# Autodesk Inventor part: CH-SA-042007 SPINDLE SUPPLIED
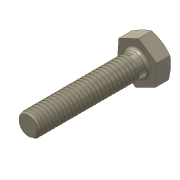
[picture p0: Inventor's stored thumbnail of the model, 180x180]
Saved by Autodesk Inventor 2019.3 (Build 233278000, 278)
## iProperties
Created: 2012-09
Part Number: CH-SA-042007 SPINDLE SUPPLIED
Material: Ogólny
Document SubType Name: Modeling
Designer: CADENGINEERING4
Density: 1 g/cm^3
Appearance: Jasnobeżowa
Author: CADENGINEERING4
Revision Number: ÈÎºÎ
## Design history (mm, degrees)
feature "ÇÐ³ý-É¨Ãè1"
node "Bryła1"
